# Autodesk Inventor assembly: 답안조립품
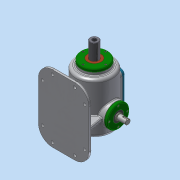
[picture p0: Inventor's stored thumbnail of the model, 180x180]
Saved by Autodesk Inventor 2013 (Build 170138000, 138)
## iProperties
Created: 2019-10
Part Number: 답안조립품
Document SubType Name: Assembly
Designer: Administrator
Mass: 5070.84 g
Surface Area: 4928.07 cm^2
Volume: 2176.15 cm^3
Density: 2.33019 g/cm^3
Author: Administrator
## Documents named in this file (17)
- C:\Users\Administrator\Desktop\391004V1040\답안조립품.iam
- C:\Users\Administrator\Desktop\391004V1040\본체.ipt
- C:\Users\Administrator\Desktop\391004V1040\가변스프링.ipt
- C:\Users\Administrator\Desktop\391004V1040\개스킷 A.ipt
- C:\Users\Administrator\Desktop\391004V1040\개스킷 B.ipt
- C:\Users\Administrator\Desktop\391004V1040\고정플레이트.ipt
- C:\Users\Administrator\Desktop\391004V1040\베어링 6205.ipt
- 베어링 6205.ipt
- C:\Users\Administrator\Desktop\391004V1040\볼트 M4x0.7.ipt
- C:\Users\Administrator\Desktop\391004V1040\부시.ipt
- C:\Users\Administrator\Desktop\391004V1040\상부커버.ipt
- C:\Users\Administrator\Desktop\391004V1040\슬라이드 커버.ipt
- C:\Users\Administrator\Desktop\391004V1040\슬라이드.ipt
- C:\Users\Administrator\Desktop\391004V1040\오일 실 25 38 8.ipt
- C:\Users\Administrator\Desktop\391004V1040\육각머리볼트 M4.ipt
- C:\Users\Administrator\Desktop\391004V1040\축 커버.ipt
- C:\Users\Administrator\Desktop\391004V1040\편심축.ipt
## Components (17 placed, 5 different names)
1. 개스킷 A:1
2. 개스킷 B:1
3. 고정플레이트:1 — 플러쉬:39
4. 개스킷 B:2
5. 가변스프링:1
6. M4x0.7:2
7. M4x0.7:1
8. M4x0.7:3
9. M4x0.7:4
10. M4x0.7:5
11. M4x0.7:6
12. M4x0.7:7
13. M4x0.7:8
14. M4x0.7:9
15. M4x0.7:10
16. M4x0.7:11
17. M4x0.7:12
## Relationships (1: Flush 1)
- 플러쉬:39 [Flush]: 고정플레이트:1
